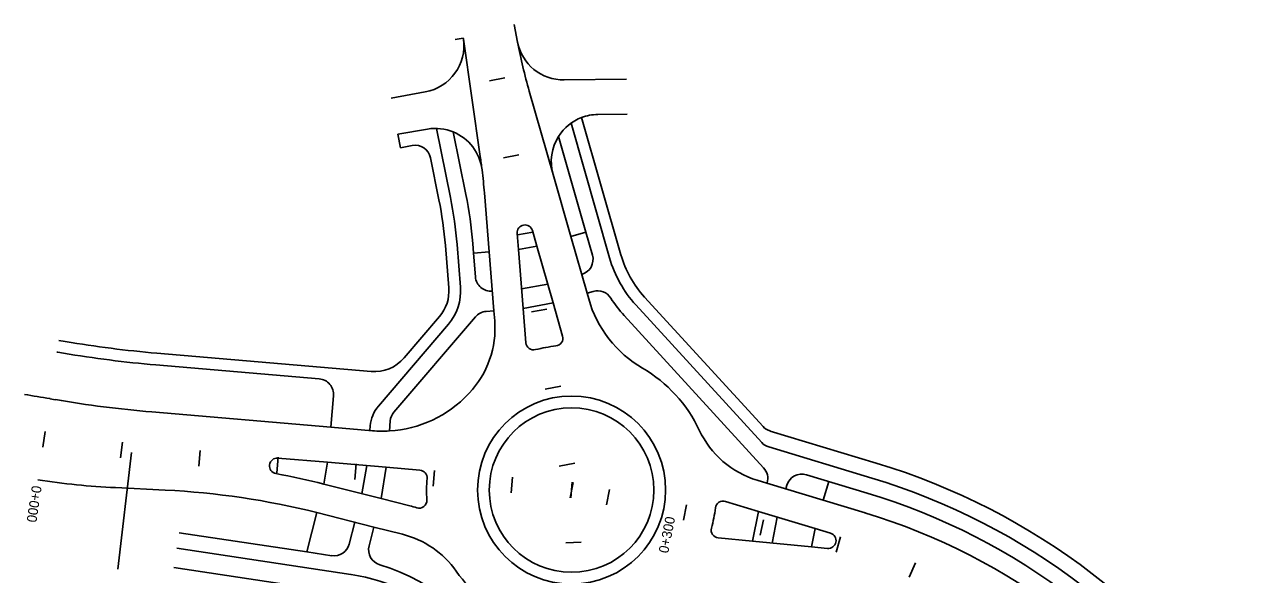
# Model space of a CAD drawing. Extents: x 6503541 to 6503743, y 5888004 to 5888145.
# Drawn here: x 6503692.267 to 6503696.036, y 5888112.224 to 5888113.908 of the extents above; entities that cross this region are included whole.
import ezdxf

# ---------------------------------------------------------------- set-up
doc = ezdxf.new("R2010")
doc.units = 0
doc.layers.add('12', color=7, linetype='Continuous')

msp = doc.modelspace()

# ---------------------------------------------------------------- linework, layer by layer
at = {"layer": '12'}
for p, q in [((6503693.7766, 5888113.8544), (6503693.7661, 5888113.9083)), ((6503693.6105, 5888113.8665), (6503693.5858, 5888113.8626)), ((6503693.6109, 5888113.8641), (6503693.6105, 5888113.8665)), ((6503693.6626, 5888113.5044), (6503693.6109, 5888113.8641)), ((6503694.1104, 5888113.7416), (6503693.9199, 5888113.7389)), ((6503693.3899, 5888113.6833), (6503693.4938, 5888113.7019)), ((6503693.8126, 5888113.7043), (6503693.8854, 5888113.4495)), ((6503693.9729, 5888113.6237), (6503694.0931, 5888113.2033)), ((6503694.0224, 5888113.633), (6503694.112, 5888113.634)), ((6503693.5011, 5888113.5883), (6503693.4098, 5888113.5729)), ((6503693.5713, 5888113.3784), (6503693.5288, 5888113.5902)), ((6503693.6184, 5888113.3878), (6503693.5799, 5888113.5794)), ((6503693.9405, 5888113.6064), (6503694.0584, 5888113.1934)), ((6503693.4183, 5888113.5307), (6503693.4098, 5888113.5729)), ((6503693.9021, 5888113.5659), (6503693.986, 5888113.2722)), ((6503693.4538, 5888113.5377), (6503693.4183, 5888113.5307)), ((6503693.536, 5888113.3713), (6503693.5102, 5888113.5)), ((6503693.8854, 5888113.4495), (6503693.9399, 5888113.259)), ((6503693.6896, 5888113.2119), (6503693.6751, 5888113.3927)), ((6503693.8224, 5888113.2771), (6503693.836, 5888113.2293)), ((6503693.7793, 5888113.2191), (6503693.7754, 5888113.2686)), ((6503693.986, 5888113.2722), (6503693.9399, 5888113.259)), ((6503693.9399, 5888113.259), (6503693.9895, 5888113.0851)), ((6503693.986, 5888113.2722), (6503694.006, 5888113.2021)), ((6503693.5661, 5888113.1013), (6503693.5557, 5888113.2312)), ((6503693.602, 5888113.1042), (6503693.5915, 5888113.2341)), ((6503693.6418, 5888113.208), (6503693.6394, 5888113.2379)), ((6503693.6418, 5888113.208), (6503693.6896, 5888113.2119)), ((6503693.6476, 5888113.1354), (6503693.6418, 5888113.208)), ((6503693.7041, 5888113.0316), (6503693.6896, 5888113.2119)), ((6503693.7793, 5888113.2191), (6503693.836, 5888113.2293)), ((6503693.7938, 5888113.0388), (6503693.7793, 5888113.2191)), ((6503693.836, 5888113.2293), (6503693.8857, 5888113.0554)), ((6503693.789, 5888113.0989), (6503693.8691, 5888113.1134)), ((6503694.0087, 5888113.0905), (6503693.9895, 5888113.0851)), ((6503693.7938, 5888113.0388), (6503693.8857, 5888113.0554)), ((6503693.8857, 5888113.0554), (6503693.9147, 5888112.954)), ((6503693.9895, 5888113.0851), (6503693.9945, 5888113.0677)), ((6503694.5286, 5888112.6767), (6503694.1655, 5888113.0736)), ((6503693.3982, 5888112.7211), (6503693.6477, 5888113.0131)), ((6503693.4296, 5888112.8871), (6503693.5377, 5888113.0137)), ((6503693.6802, 5888113.0296), (6503693.7041, 5888113.0316)), ((6503693.7066, 5888113.0006), (6503693.7041, 5888113.0316)), ((6503693.8023, 5888112.9337), (6503693.7938, 5888113.0388)), ((6503694.5303, 5888112.5504), (6503694.1035, 5888113.0169)), ((6503694.5246, 5888112.6277), (6503694.139, 5888113.0493)), ((6503693.3508, 5888112.7395), (6503693.5651, 5888112.9903)), ((6503692.3716, 5888112.9406), (6503692.3918, 5888112.9372)), ((6503692.3662, 5888112.9048), (6503692.3685, 5888112.9046)), ((6503692.3685, 5888112.9046), (6503692.3858, 5888112.9017)), ((6503692.6723, 5888112.9015), (6503693.3281, 5888112.8455)), ((6503692.6692, 5888112.8656), (6503693.1691, 5888112.8229)), ((6503692.3448, 5888112.762), (6503692.3616, 5888112.7591)), ((6503693.2128, 5888112.771), (6503693.2046, 5888112.6747)), ((6503692.6569, 5888112.7215), (6503693.2046, 5888112.6747)), ((6503693.2046, 5888112.6747), (6503693.3324, 5888112.6638)), ((6503693.3254, 5888112.6786), (6503693.3242, 5888112.6645)), ((6503693.3869, 5888112.694), (6503693.3843, 5888112.6631)), ((6503694.5501, 5888112.6631), (6503694.8754, 5888112.5648)), ((6503694.5461, 5888112.6142), (6503694.8615, 5888112.5188)), ((6503693.043, 5888112.5802), (6503693.1948, 5888112.5672)), ((6503693.1948, 5888112.5672), (6503693.1836, 5888112.5006)), ((6503693.1948, 5888112.5672), (6503693.3747, 5888112.5518)), ((6503693.3148, 5888112.5569), (6503693.3003, 5888112.471)), ((6503693.3747, 5888112.5518), (6503693.3586, 5888112.4562)), ((6503693.3747, 5888112.5518), (6503693.4776, 5888112.543)), ((6503694.6612, 5888112.5292), (6503694.8476, 5888112.4729)), ((6503692.6975, 5888112.4821), (6503692.5454, 5888112.4896)), ((6503693.1836, 5888112.5006), (6503693.3586, 5888112.4562)), ((6503694.5107, 5888112.5121), (6503694.5405, 5888112.5031)), ((6503694.5408, 5888112.5041), (6503694.5405, 5888112.5031)), ((6503694.5405, 5888112.5031), (6503694.7126, 5888112.451)), ((6503694.6014, 5888112.4972), (6503694.5979, 5888112.4857)), ((6503694.7301, 5888112.5084), (6503694.7128, 5888112.451)), ((6503693.3586, 5888112.4562), (6503693.4466, 5888112.4338)), ((6503694.7125, 5888112.451), (6503694.8407, 5888112.4123)), ((6503693.1314, 5888112.2926), (6503693.162, 5888112.4132)), ((6503693.162, 5888112.4132), (6503693.3365, 5888112.3689)), ((6503694.4135, 5888112.4474), (6503694.5144, 5888112.4169)), ((6503694.5144, 5888112.4169), (6503694.4964, 5888112.3253)), ((6503694.5144, 5888112.4169), (6503694.6876, 5888112.3646)), ((6503693.2613, 5888112.3168), (6503693.2783, 5888112.3837)), ((6503694.5721, 5888112.3995), (6503694.5564, 5888112.3196)), ((6503693.1315, 5888112.2925), (6503692.7405, 5888112.3512)), ((6503693.3218, 5888112.3111), (6503693.3365, 5888112.3689)), ((6503693.3365, 5888112.3689), (6503693.4244, 5888112.3466)), ((6503694.4964, 5888112.3253), (6503694.3914, 5888112.3354)), ((6503694.6876, 5888112.3646), (6503694.6764, 5888112.3081)), ((6503694.6876, 5888112.3646), (6503694.7351, 5888112.3502)), ((6503693.2666, 5888112.2237), (6503692.7334, 5888112.3037)), ((6503694.6764, 5888112.3081), (6503694.4964, 5888112.3253)), ((6503694.7259, 5888112.3033), (6503694.6764, 5888112.3081)), ((6503693.2077, 5888112.2811), (6503693.1314, 5888112.2926)), ((6503693.2577, 5888112.1644), (6503692.7245, 5888112.2444))]:
    msp.add_line(p, q, dxfattribs=at)
for points in [[(6503693.7377, 5888113.7449), (6503693.6905, 5888113.7364)], [(6503693.7805, 5888113.5088), (6503693.7333, 5888113.5002)], [(6503693.8233, 5888113.2726), (6503693.7761, 5888113.2641)], [(6503693.8661, 5888113.0365), (6503693.8189, 5888113.0279)], [(6503693.9089, 5888112.8003), (6503693.8617, 5888112.7918)], [(6503692.3297, 5888112.6613), (6503692.3226, 5888112.6139)], [(6503692.5609, 5888112.5809), (6503692.5668, 5888112.6285)], [(6503692.8004, 5888112.5557), (6503692.8046, 5888112.6035)], [(6503692.5949, 5888112.5973), (6503692.5529, 5888112.2398)], [(6503693.0396, 5888112.5352), (6503693.0437, 5888112.583)], [(6503693.2787, 5888112.5148), (6503693.2828, 5888112.5626)], [(6503693.9517, 5888112.5642), (6503693.9044, 5888112.5556)], [(6503693.5179, 5888112.4944), (6503693.522, 5888112.5422)], [(6503693.757, 5888112.4739), (6503693.7611, 5888112.5217)], [(6503693.9375, 5888112.4586), (6503693.9468, 5888112.5057)], [(6503693.9375, 5888112.4586), (6503693.9468, 5888112.5057)], [(6503693.9442, 5888112.5061), (6503693.9401, 5888112.4583)], [(6503693.9442, 5888112.5061), (6503693.9401, 5888112.4583)], [(6503694.0584, 5888112.4837), (6503694.0492, 5888112.4366)], [(6503694.2846, 5888112.3902), (6503694.2939, 5888112.4373)], [(6503694.5294, 5888112.3909), (6503694.5201, 5888112.3438)], [(6503694.7654, 5888112.3386), (6503694.7526, 5888112.2923)], [(6503693.972, 5888112.3222), (6503693.9241, 5888112.3204)], [(6503694.9949, 5888112.2591), (6503694.9764, 5888112.2148)]]:
    msp.add_lwpolyline(points, dxfattribs=at)
for radius in [0.288, 0.252]:
    msp.add_circle((6503693.9421, 5888112.4822), radius, dxfattribs=at)
for centre, radius, start, end in [((6503693.4683, 5888113.8437), 0.144, 280.1777, 8.1788), ((6503693.9178, 5888113.8828), 0.144, 190.9965, 270.8155), ((6503695.5434, 5888114.1987), 1.8, 191.0271, 195.9437), ((6503694.0239, 5888113.489), 0.144, 110.7239, 147.7541), ((6503694.0239, 5888113.489), 0.144, 90.6008, 110.7239), ((6503693.525, 5888113.4463), 0.144, 67.5986, 99.5452), ((6503693.525, 5888113.4463), 0.144, 6.8648, 67.5986), ((6503694.0239, 5888113.489), 0.144, 147.7541, 195.9437), ((6503693.4631, 5888113.4906), 0.048, 11.3593, 101.1209), ((6503691.8809, 5888113.2483), 1.8, 6.8648, 8.1788), ((6503691.8809, 5888113.2483), 1.8, 4.5991, 6.8648), ((6503692.3595, 5888113.135), 1.2, 4.5991, 11.3578), ((6503692.3595, 5888113.135), 1.236, 4.5991, 11.3578), ((6503692.3595, 5888113.135), 1.284, 4.5991, 11.3578), ((6503693.7993, 5888113.2705), 0.024, 15.9437, 184.5991), ((6503693.9599, 5888113.1889), 0.048, 285.9437, 15.9437), ((6503694.4046, 5888113.2923), 0.324, 195.9441, 222.4508), ((6503694.4046, 5888113.2923), 0.36, 195.9437, 222.4508), ((6503693.6955, 5888113.1392), 0.048, 184.5991, 274.5991), ((6503693.4465, 5888113.0917), 0.12, 319.4931, 4.5991), ((6503693.4465, 5888113.0917), 0.156, 319.4931, 4.5982), ((6503694.0219, 5888113.0444), 0.048, 32.9297, 105.9437), ((6503694.3407, 5888113.1666), 0.36, 195.9437, 239.7903), ((6503694.4046, 5888113.2923), 0.408, 212.9297, 222.4508), ((6503693.6841, 5888112.9818), 0.048, 94.5991, 139.4931), ((6503693.4196, 5888112.9775), 0.288, 316.5364, 4.5991), ((6503693.8916, 5888112.9475), 0.024, 276.2021, 15.9437), ((6503692.9634, 5888116.3085), 3.4554, 260.3766, 265.1162), ((6503692.9634, 5888116.3085), 3.4194, 260.3766, 265.1162), ((6503693.8262, 5888112.9356), 0.024, 184.5991, 284.3407), ((6503693.9421, 5888112.4822), 0.444, 96.2021, 104.3407), ((6503693.3383, 5888112.965), 0.12, 265.1162, 319.4931), ((6503693.9421, 5888112.4822), 0.432, 25.1103, 59.7914), ((6503693.165, 5888112.7751), 0.048, 355.1162, 85.1162), ((6503693.2561, 5888118.6079), 5.916, 260.37658, 261.13944), ((6503692.9634, 5888116.3085), 3.6, 260.3766, 265.1162), ((6503693.3631, 5888113.0225), 0.36, 273.3712, 316.9818), ((6503693.9421, 5888112.4822), 0.432, 136.5355, 136.9818), ((6503693.433, 5888112.6694), 0.108, 139.4931, 175.1162), ((6503693.4347, 5888112.6899), 0.048, 139.4931, 175.1162), ((6503694.564, 5888112.7091), 0.048, 222.4508, 253.1735), ((6503693.3631, 5888113.0225), 0.36, 265.1162, 273.3712), ((6503694.5941, 5888112.7877), 0.288, 205.1108, 253.1735), ((6503694.56, 5888112.6601), 0.048, 222.4508, 253.1735), ((6503693.0409, 5888112.5562), 0.024, 85.1162, 259.4225), ((6503694.2744, 5888110.5777), 2.076, 31.9347, 73.1735), ((6503692.5795, 5888110.085), 2.49, 75.9592, 79.4225), ((6503693.4756, 5888112.5191), 0.024, 355.4753, 85.1162), ((6503694.4949, 5888112.518), 0.048, 343.1735, 42.4508), ((6503694.6473, 5888112.4833), 0.048, 73.1735, 163.1735), ((6503692.6634, 5888114.8866), 2.4, 261.4707, 267.1813), ((6503693.9421, 5888112.4822), 0.444, 175.4753, 183.8677), ((6503694.2744, 5888110.5777), 2.028, 31.9347, 73.1735), ((6503692.5795, 5888110.085), 2.4, 75.9523, 87.1813), ((6503693.4752, 5888112.4506), 0.024, 252.3894, 3.8677), ((6503694.4066, 5888112.4245), 0.024, 73.1735, 172.9152), ((6503694.2744, 5888110.5777), 1.98, 31.9347, 73.1735), ((6503693.3536, 5888112.0675), 0.378, 72.3894, 75.7602), ((6503693.9421, 5888112.4822), 0.444, 344.7765, 352.9152), ((6503694.2849, 5888110.5745), 1.92, 31.9347, 73.1735), ((6503693.3536, 5888112.0675), 0.288, 35.1711, 75.7602), ((6503694.3937, 5888112.3593), 0.024, 164.7765, 264.5182), ((6503694.7282, 5888112.3272), 0.024, 264.5182, 73.1735), ((6503693.2148, 5888112.3286), 0.048, 261.4707, 345.7602), ((6503693.3683, 5888112.2993), 0.048, 165.7602, 253.544), ((6503693.1848, 5888111.6778), 0.552, 7.7722, 81.4707), ((6503693.1848, 5888111.6778), 0.6, 23.5192, 73.544), ((6503693.9421, 5888112.4822), 0.432, 215.1701, 231.6188)]:
    msp.add_arc(centre, radius, start, end, dxfattribs=at)

# ---------------------------------------------------------------- texts
for s, rotation, p in [('0+000', 261.4707, (6503692.2899, 5888112.4974)), ('0+300', 78.8458, (6503694.2378, 5888112.2869))]:
    msp.add_text(s, height=0.03, rotation=rotation, dxfattribs=at).set_placement(p)

doc.saveas('drawing.dxf')
